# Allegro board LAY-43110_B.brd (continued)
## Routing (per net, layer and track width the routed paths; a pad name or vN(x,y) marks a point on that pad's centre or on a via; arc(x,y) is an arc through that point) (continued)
P1V8_3V3_BRD: length 233
  TOP w0.254: C35.1 74.46,28.68 71.92,28.68 71.5,29.1 U11.1 ; U7.8 17.79,33.71 C22.1 ; U17.6 19.56,18.97 19.7,19.1 19.95,19.1 20.59,19.74 v1(20.59,19.86) ; U12.6 18.97,30.28 C31.1 20.08,30.28 v1(20.71,30.91) ; v1(19.82,16.81) 19.82,16.69 C62.1 20.45,16.04 U20.6
  TOP w0.381: C22.1 18.05,32.94 v1(18.3,32.69)
  TOP w0.508: v1(18.3,32.69) 18.55,32.44 20.21,32.44 20.71,31.93 v1(20.71,30.91) ; C75.1 52.95,2.59 ; v1(71.92,25.76) 73.62,27.46 v1(73.62,27.99) 74.46,27.99 74.76,28.29 ; R21.1 R17.1 ; R17.1 v1(61.35,39.8) ; R17.1 R14.1 ; 74.76,28.29 74.89,28.17 76.95,28.17 77.91,29.13 77.91,32.61 v1(77.99,32.69) ; 74.76,28.29 C35.1 ; R39.1 61.4,32.33 61.4,29.03 v1(61.33,28.96) 61.73,28.55 R60.1 61.73,27.89 63.84,25.78 64,25.78 v1(64.02,25.76) ; R44.1 R41.1 77.48,33.2 v1(77.99,32.69) ; v1(77.99,32.69) 77.99,33.17 80.02,35.2 R30.1 88.46,35.2 v2(88.68,34.98) ; v1(72.63,35.64) 71.67,35.64 R32.1 ; v1(73.8,39.42) 73.8,39.7 C13.1 U3.6 ; R46.1 v1(63.94,31.88) ; R36.1 v1(91.55,35.51) ; v1(91.55,42.44) R9.1
  INT_1 w0.508: v2(88.68,34.98) 88.81,34.85 90.89,34.85 v1(91.55,35.51) v1(91.55,42.44) ; v1(73.62,27.99) 73.14,27.99 72.63,28.5 v1(72.63,35.64) 72.63,37.46 73.83,38.67 73.83,39.39 v1(73.8,39.42) ; v1(20.46,12.88) 23,12.88 24.88,11 32.63,11 34.94,8.69 45.1,8.69 46.24,7.54
  INT_1 w0.762: 46.24,7.54 48.83,4.95 51.17,4.95 52.95,3.17 52.95,2.59 54.93,4.57 56.73,4.57 58.03,3.28 58.03,2.59
  BOTTOM w0.508: v1(63.94,31.88) 61.33,29.26 v1(61.33,28.96) 61.07,28.7 59.17,28.7 57.29,26.82 52.06,26.82 51.12,25.88 SH17.2 v2(51.12,22) 51.12,21.44 54.75,17.81 61.28,17.81 67.32,11.76 67.32,8.97 68.23,8.06 68.95,8.06 J28.2 69.28,7.21 67.68,5.61 59.6,5.61 58.08,4.09 58.08,2.64 58.03,2.59 ; v1(73.8,39.42) 73.55,39.42 72.15,40.82 63.18,40.82 62.17,39.8 v1(61.35,39.8) ; v1(20.46,12.88) 19.82,13.51 v1(19.82,16.81) 19.82,18.47 20.59,19.23 v1(20.59,19.86) 19.44,21.01 19.44,29.64 v1(20.71,30.91) ; v1(71.92,25.76) v1(64.02,25.76)
P3V3_BATT: length 6.6
  TOP w0.508: D10.A 30.11,15.26 v1(30.54,15.7)
  BOTTOM w0.508: BT1.1 30.01,15.16 v1(30.54,15.7)
P3V3_LDO: length 62.1
  TOP w0.279: C39.1 68.8,26.29 69.16,26.65 U11.14
  TOP w0.508: v1(47.94,19.25) 52.82,19.25 53.48,18.59 61.73,18.59 63.51,20.37 63.51,22.4 66.81,25.7 C38.1 C39.1
  TOP w1.016: v1(47.94,19.25) 47.94,20.07 46.11,21.89 D8.C
  BOTTOM w1.016: J35.1 59.83,10.04 59.83,14.4 59.14,15.09 49.75,15.09 47.94,16.89 v1(47.94,19.25)
P3V3_SDA: length 159.3
  TOP w0.254: J14.1 C43.1 49.42,23.67 50.05,24.31 50.05,26.59 50.94,27.48 v1(51.07,27.48) ; R1.2 14.52,51.36 14.87,51.36 v1(15.13,51.1) ; v1(55.79,28.37) 55.89,28.47 R55.1 ; R5.1 v1(16.14,48.18) ; U4.1 52.62,39.9 C11.1 ; v1(50.66,41.1) 50.1,41.1 49.67,41.53 R10.1 ; v1(13.75,47.14) 13.3,47.6 C3.1 U1.1
  TOP w0.305: U6.7 52.8,34.66 52.69,34.54 v1(52.69,33.83) ; U5.7 39.92,37.2 39.61,36.9 v1(39.61,36.63) ; v1(52.69,30.84) 52.81,30.72 U13.1 ; U14.1 52.81,25.21 52.69,25.32 v1(52.69,25.86) ; U8.5 v1(46.8,34.16) ; U5.11 v1(42.19,35.2) ; v1(40.54,40.87) U5.1
  TOP w0.381: 39.69,41.68 C8.1 40.2,41.17 ; 36.49,41.3 C9.1 ; C9.1 37,40.79 ; C9.1 37.5,41.3 ; 39.99,40.54 U5.1 39.99,40.37 ; 38.72,40.41 C10.1 ; C10.1 37.96,41.05 ; C10.1 39.48,41.05
  TOP w0.508: v1(13.75,47.14) 14.24,46.66 R8.1 ; C11.1 v1(50.66,41.1) ; R43.1 v1(43.83,31.6) ; R42.1 v1(49.92,33.71) ; v1(56.73,40.51) 56.73,40.23 R16.1 ; v1(46.8,34.16) C20.1 ; v1(39.61,34.32) 40.14,33.78 R38.1 ; C29.1 v1(52.69,30.84) ; C42.1 51.65,25.86 v1(52.69,25.86) ; v1(18.55,40.54) 34.07,40.54 v1(34.4,40.21) ; C25.1 v1(52.69,33.83) ; v1(55.69,25.07) R65.1 ; R66.1 v1(44.39,24.69)
  INT_1 w0.254: v1(55.69,25.07) 56.35,25.73 56.35,27.81 v1(55.79,28.37)
  INT_1 w0.508: v1(43.83,31.6) 43.78,30.78 44.39,30.18 v1(44.39,24.69) ; v1(40.54,40.87) 40.54,37.86 39.61,36.93 v1(39.61,36.63) v1(39.61,34.32) ; v1(50.66,41.1) 51.45,41.1 52.69,39.85 v1(52.69,33.83) v1(52.69,30.84) 52.69,29.11 v1(51.07,27.48) v1(52.69,25.86) 52.69,25.48 53.61,24.56 55.26,24.56 55.69,24.99 v1(55.69,25.07)
  BOTTOM w0.508: v1(39.61,34.32) 41.3,34.32 v1(42.19,35.2) 43.23,34.16 v1(46.8,34.16) ; v1(40.54,40.87) 40.53,40.86 40.53,38.66 39.17,37.3 36.72,37.3 36.21,37.81 36.21,38.68 34.68,40.21 v1(34.4,40.21) ; v1(40.54,40.87) 39.74,40.87 SH16.1 ; v1(40.54,40.87) 41.17,40.87 41.88,40.16 48.78,40.16 49.72,41.1 v1(50.66,41.1) 51.63,41.1 53.2,39.52 54.57,39.52 55.56,40.51 v1(56.73,40.51) ; v1(15.13,51.1) 15.63,51.1 16.14,50.6 v1(16.14,48.18) 15.84,47.88 14.31,47.88 13.75,47.32 v1(13.75,47.14) 16.27,44.63 16.27,42.82 v1(18.55,40.54) ; v1(49.92,33.71) 49.72,33.91 49.54,33.91 48.6,34.85 47.49,34.85 v1(46.8,34.16) ; v1(46.8,34.16) 46.8,33.28 45.11,31.6 v1(43.83,31.6)
P5V: length 45.1
  TOP w0.254: U12.1 18.16,30.68 17.93,30.91 C32.1 ; v1(16.17,19.61) C54.1 17.16,19.61 17.8,18.97 U17.1 ; C24.1 17.19,33.61 U7.7 ; R50.1 v1(16.98,36.88) ; C61.1 17.42,16.04 U20.1
  TOP w0.381: R71.1 21.86,20.24 21.09,21.01 v1(20.59,21.01) ; C61.1 v1(17.41,16.81)
  TOP w0.508: C32.1 17.16,31.04 16.65,31.55 R45.2 16.4,31.17 v1(15.89,30.66) 15.38,30.15 R54.2 ; C41.1 9.16,24.82 9.03,24.82 ; C41.1 9.41,23.67 ; C41.1 10.3,24.88 ; C41.1 9.66,23.04 9.16,23.04 ; v1(8.78,19.48) 8.14,19.48 C53.1 8.78,18.34 U19.5 ; U15.4 22.24,23.67 v1(22.8,24.23) ; v1(16.01,17.83) 16.4,17.45 C59.1 U19.3 ; v1(28.21,26.47) 27.95,26.21 D13.A ; C24.1 v1(16.27,33.45)
  TOP w1.016: C41.1 U15.2 U15.4
  BOTTOM w0.508: v1(28.21,26.47) 27.95,26.21 24.85,26.21 22.87,24.23 v1(22.8,24.23)
  vias: v1(8.52,26.85) v1(8.52,25.7) v1(8.52,24.31) v1(8.52,23.16)
P5V0_SDA_USB_CONN_VBUS: length 5.4
  TOP w0.381: J11.1 5.88,43.39 TP5.1
  TOP w0.508: L1.1 7.96,45.29 D14.C 6.36,45.17 TP5.1
P5V_LDO_OUT: length 2.9
  TOP w0.508: 25.98,3.48 J34.3 ; J34.3 26.94,4.43 ; J34.3 26.94,2.53
P5V_SDA: length 53.3
  TOP w0.381: 35.22,36.02 37.88,36.02 39.57,37.71 U5.6
  TOP w0.508: R56.1 v1(42.58,30.48) R48.1 ; v1(33.41,30.53) 33.41,30.02 33.97,29.46 R52.1
  TOP w0.635: U9.1 35.21,32.8 ; C21.1 35.29,34.49
  TOP w1.016: v1(16.4,39.55) 33.54,39.55 33.9,39.19 33.9,39.01 ; C5.1 11.32,44.98 v1(11.32,45.77) 10.39,45.77 L1.2
  BOTTOM w0.508: v1(42.58,30.48) 38.32,30.48 37.35,29.51 34.18,29.51 33.41,30.28 v1(33.41,30.53)
  BOTTOM w0.635: v1(42.58,30.48) 44.4,30.48 TP35.1
  BOTTOM w1.016: v1(16.4,39.55) 15.63,39.55 14.62,40.56 14.62,42.72 11.57,45.77 v1(11.32,45.77)
P5V_SDA_PSW: length 15.5
  TOP w0.508: U9.6 v1(38.68,33.66)
  TOP w0.635: D3.A 27.24,34.27 D4.A 31.41,34.27 31.51,34.36 v1(32.58,34.36)
  BOTTOM w0.508: TP29.1 38.68,35.07 v1(38.68,33.66)
  BOTTOM w0.635: v1(38.68,33.66) 33.87,33.66 33.16,34.36 v1(32.58,34.36)
P5V_USB: length 69.6
  TOP w0.508: v1(25.03,8.31) 25.39,7.95 25.39,6.68 D12.C
  BOTTOM w0.508: v1(27.95,30.25) 25.82,28.12 22.87,28.12 21.48,26.72 21.48,15.54 25.03,11.99 v1(25.03,8.31) 25.03,7.47 25.69,6.81 41.77,6.81 47.66,0.91 58.89,0.91 60.57,2.59
P12V: length 46.7
  TOP w1.016: J32.1 21.35,8.81 19.95,7.42 10.05,7.42 9.16,8.31 D11.A 9.41,9.7 v1(10.55,9.7)
  INT_1 w1.016: v1(10.55,9.7) 3.57,9.7 J23.3 3.82,13 3.82,28.09 2.4,29.51 J13.2
P12V_VBAT: length 5.9
  TOP w0.508: U10.7 C33.1
  TOP w0.762: U10.7 9.54,30.28 9.56,30.3
  TOP w1.016: 9.16,12.24 D11.C 8.36,12.25 7.46,11.35 C68.1
VDD_1P45OUT_PMCIN: length 5.5
  TOP w0.254: 85.13,12.88 85.13,13.66 U18.15
  TOP w0.381: C66.1 84.11,11.13 85.13,12.14 85.13,12.88
  TOP w0.508: L5.1 83.76,10.41 C66.1
VDD_BRD: length 80.2
  TOP w0.381: v1(83.17,12.04) 83.76,12.62 C64.1 83.76,13.67 84.13,14.04 U18.13
  TOP w0.508: R69.1 v1(79.54,22.78)
  TOP w1.016: J29.1 J28.1 69.23,10.97 J27.1
  INT_1 w0.254: J12.1 59.91,28.14 59.55,27.79 59.55,22.28 58.84,21.56 56.76,21.56 55.26,20.07 52.31,20.07 51.73,19.48 50.97,19.48 49.7,18.21 49.7,13.67 53.02,10.34 55.65,10.34 J24.3
  INT_1 w0.508: v1(79.54,22.78) 79.54,21.77 81.6,19.71 81.6,14.45 83.17,12.88 v1(83.17,12.04) 83.17,11.79 81.47,10.08 73.42,10.08 J29.1
  BOTTOM w0.508: J24.3 59.02,8.4 60.46,6.96 62.85,6.96 64.2,8.31 64.2,9.68 J27.1
VDD_MCU: length 37.6
  TOP w0.152: U18.44 86.13,21.16
  TOP w0.254: 86.13,21.16 86.13,21.65 ; U18.20 87.63,13.27 C65.1 87.9,12.88 v1(88.28,12.88)
  TOP w0.381: v1(85.15,23.01) 85.42,22.75 C44.1 85.97,22.24 86.13,22.07 86.13,21.65
  TOP w0.508: v1(89.73,12.57) 91.63,12.57 L4.1
  INT_1 w0.508: 85.85,13.02 83.78,15.09 83.78,21.64 v1(85.15,23.01) ; 85.85,13.02 88.14,13.02 v1(88.28,12.88) 88.4,13 89.12,13 89.55,12.57 v1(89.73,12.57) ; 85.85,13.02 85.85,12.87 81.8,8.81 73.01,8.81 J29.2
VDD_RF: length 36.8
  TOP w0.254: U18.32 91.33,18.56 v1(91.48,18.41) 91.68,18.41 92,18.1 C78.1
  TOP w0.279: U18.35 90.81,20.06 C46.1 91.45,20.76 90.95,20.76 90.75,20.56 U18.36
  TOP w0.508: C46.1 91.48,21.36 v1(91.33,21.51) 91.76,21.95 C87.1 C86.1 91.78,23.36 91.78,24.36 91.12,25.02 v1(85.18,25.02)
  INT_1 w0.254: v1(91.48,18.41) 90.23,18.41 89.83,18.82 89.83,20.02 v1(91.33,21.51)
  INT_1 w0.508: v1(85.18,25.02) 84.54,25.02 83.2,23.67 79.08,23.67 78.04,22.63 78.04,21.31 76.53,19.8 74.32,19.8 J31.2
VDD_RFF: length 15.6
  TOP w0.508: L5.2 C67.1 80.43,9.88 79.79,10.52 v1(79.79,11.1)
  INT_1 w0.508: v1(79.79,11.1) 78.68,12.22 76.03,12.22 J31.1
  INT_1 w1.016: J30.2 J31.1
VDDA: length 5.1
  TOP w0.254: C69.1 91.63,16.56 U18.28
  TOP w0.381: C69.1 92.21,16.08 92.77,15.52 92.77,14.73 L4.2
A0: length 3
  TOP w0.152: R99.2 73.04,5.26 73.04,2.82 J4.1
A1: length 2.8
  TOP w0.152: SH13.2 J4.2
A2: length 2.9
  TOP w0.152: J4.3 78.4,5.33 SH14.2
A3: length 3
  TOP w0.152: SH15.2 80.94,4.72 J4.4
A4: length 2.7
  TOP w0.152: R96.2 82.49,3.53 J4.5
A5: length 4.2
  TOP w0.152: J4.6 86.02,4.8 R100.2 R97.2
ADC0_DM0/CMP0_IN1: length 72.6
  TOP w0.152: v1(79.84,27.89) 79.77,27.97 79.77,33.2 80.43,33.86 89.07,33.86 90.21,35 90.21,37.62 89.42,38.4 88.25,38.4 87.9,38.76 R19.1 ; R97.1 84.42,6.32 84.9,5.84 85.18,5.84 v1(85.23,5.79) 85.36,5.92 85.36,6.88 84.37,7.87 81.57,7.87 81.29,8.15 75.96,8.15 v1(75.37,7.57) ; v1(91.07,14.25) 90.61,14.25 90.34,14.52 U18.25
  INT_1 w0.152: v1(91.07,14.25) 91.4,13.92 91.4,10.87 90,9.47 88.96,9.47 85.28,5.79 v1(85.23,5.79)
  BOTTOM w0.152: v1(79.84,27.89) 79.03,27.08 76.44,27.08 75.15,25.78 75.15,7.8 v1(75.37,7.57)
ADC0_DP0/CMP0_IN0: length 70.3
  TOP w0.152: v1(78.85,27.99) 79.26,28.4 79.26,33.35 80.18,34.26 88.96,34.26 89.79,35.09 89.79,37.48 89.24,38.02 88.2,38.02 87.9,37.72 R25.1 ; R99.1 74.69,6.17 74.84,6.32 v1(75.04,6.32) ; v1(90.91,13.46) 90.8,13.46 90.45,13.82 89.83,13.82 89.63,14.01 U18.24
  INT_1 w0.152: v1(75.04,6.32) 75.12,6.32 75.76,5.69 84.47,5.69 88.61,9.83 89.78,9.83 90.91,10.96 v1(90.91,13.46)
  BOTTOM w0.152: v1(75.04,6.32) 74.78,6.59 74.78,26.17 76.09,27.48 78.35,27.48 v1(78.85,27.99)
ANT: length 3.3
  TOP w0.203: L2.1 C50.1 90.36,19.08 U18.33
BYP_FXOS8700CQ: length 4.3
  TOP w0.203: C34.1 73.95,29.24 72,29.24 71.63,29.6 U11.2
CAN_HI: length 9
  TOP w0.254: v1(6.49,14.78) 7,14.78 7.58,15.37 R77.2 U19.7
  BOTTOM w0.254: J23.1 2.04,15.67 2.93,14.78 v1(6.49,14.78)
CAN_LO: length 11.5
  TOP w0.254: U19.6 8.22,17.07 R73.1 7.58,17.27 7,16.69 v1(6.74,16.69)
  BOTTOM w0.254: 2.04,13.77 2.3,14.02 6.62,14.02 7.38,14.78 7.38,16.05 v1(6.74,16.69)
CAN_RX: length 3.4
  TOP w0.152: U17.3 16.77,17.97 16.4,18.34 U19.4
CAN_TX: length 4.7
  TOP w0.152: 14.78,14.53 15.76,14.53 16.27,14.02 18.05,14.02 18.56,14.53 U20.3
CRST_FXOS8700CQ: length 3.3
  TOP w0.203: U11.8 69.16,34.06 69.2,34.1 C19.1
CS: length 4.1
  TOP w0.152: R23.2 R21.2 TP14.1 65.84,38.79 U3.4
D0: length 8.7
  TOP w0.152: J8.2 87.52,44.88 87.52,49.31 J1.1
D1: length 4.9
  TOP w0.152: J10.2 83.45,45.94 J1.2
D2: length 3.7
  TOP w0.152: J1.3 80.91,47.68 80.92,47.66 SH11.2
D3: length 4.3
  TOP w0.152: J1.4 79.76,49.45 SH10.2
D4: length 4.2
  TOP w0.152: SH9.2 75.83,48.43 75.83,50.84
D5: length 4.2
  TOP w0.152: J1.6 73.29,48.43 SH8.2
D6: length 3.7
  TOP w0.152: J1.7 70.75,49.81 70.74,49.8 SH7.2
D7: length 3.7
  TOP w0.152: SH6.2 68.21,47.16 J1.8
D8: length 3.7
  TOP w0.152: J2.1 64.22,49.78 64.24,49.77 SH5.2
D9: length 3.7
  TOP w0.152: SH2.2 61.67,49.77 61.68,49.78 J2.2
D10: length 3.7
  TOP w0.152: J2.3 59.14,49.78 59.13,49.77 SH4.2
D11: length 5.1
  TOP w0.152: J2.4 56.6,46.5 J9.2
D12: length 8.6
  TOP w0.152: J7.2 52.34,44.52 52.34,49.09 J2.5
D13: length 4.1
  TOP w0.152: J2.6 51.52,49.28 50.29,48.04 SH1.2
D14: length 3.8
  TOP w0.152: J2.9 43.9,49.4 R7.2
D15: length 6.2
  TOP w0.152: R6.1 43.43,46.16 41.36,48.23 J2.10
DCDC_LN: length 9.8
  TOP w0.279: U18.14 v2(84.63,13.34) ; U18.12 82.54,15.06 v2(82.54,15.06) 81.98,15.06
  TOP w0.381: 81.98,15.06 81.67,15.06 79.47,12.86 L3.2
  BOTTOM w0.279: v2(84.63,13.34) 82.9,15.06 v2(82.54,15.06)
DCDC_LP: length 5.2
  TOP w0.279: 81.56,16.06 U18.10
  TOP w0.381: L3.1 78.6,16.06 81.56,16.06
EXTAL_32M: length 5.7
  TOP w0.152: U18.30 91.39,17.56 92.27,16.69 92.98,16.69 93.33,16.33 94.65,16.33 95.13,15.86 Y1.3
I2C1_SCL: length 5.2
  TOP w0.203: U11.4 72.98,30.6 TP20.1 73.09,30.61 74.28,30.61 R47.1 74.82,31.14 R44.2
I2C1_SDA: length 7.9
  TOP w0.203: R41.2 R37.1 73.42,34.21 TP17.1 70.75,33.83 70.16,33.24 U11.6
INT1_COMBO_R: length 4.2
  TOP w0.203: U11.11 66.84,30.1 R61.1
INT2_COMBO: length 3.2
  TOP w0.203: R40.2 R39.2 62.8,32.87 v1(63.51,33.58)
  BOTTOM w0.203: TP32.1 63.23,33.3 v1(63.51,33.58)
INT2_COMBO_R: length 4.1
  TOP w0.203: R40.1 66.6,31.1 U11.9
LEDRGB_BLUE: length 2
  TOP w0.254: R93.2 40.88,8.95 LED4.3
LEDRGB_GREEN: length 1.9
  TOP w0.254: LED4.4 42.42,8.99 R90.2
LEDRGB_RED: length 4.3
  TOP w0.254: LED4.1 42.41,11.98 42.41,13.61 43.22,14.43 R87.2
LIN: length 13.2
  TOP w0.254: U10.6 C28.1 2.55,31.55 J13.1
  TOP w0.508: R27.1 R34.1 3.31,34.72 2.04,33.45 J13.1
LIN_RX_LS: length 4.8
  TOP w0.152: U12.3 17.67,29.27 17.28,28.88 R54.1 15.25,29.01 13.63,29.01
LIN_SLP: length 7.3
  TOP w0.152: U7.6 16.4,35.1 15.63,34.34 15.63,32.82 15.38,32.56 R45.1 15.38,31.04 14.62,30.28 U10.2
LIN_TX_LS: length 5.5
  TOP w0.152: U10.4 14.87,32.82 15.13,33.07 15.13,34.34 16.39,35.6 U7.5
LVLRST_EN: length 1.2
  TOP w0.152: R1.1 13.35,51.36 13.3,51.31 U1.5
MIC2005_CSLEW: length 3.5
  TOP w0.254: U9.5 38.06,31.85 37.45,32.46 C21.2
P5-9V_VIN: length 75.7
  TOP w0.381: J34.1 32.97,3.48 ; J34.1 31.06,3.48 ; J34.1 32.02,4.43 ; J34.1 32.02,2.53
  TOP w0.508: v1(29.22,17.07) 29.35,16.94 29.35,14.25 28.71,13.61 28.71,12.78 26.81,10.87 v1(26.81,7.8) ; D6.A v1(28.21,28.65)
  INT_1 w0.508: v1(28.21,28.65) 28.46,28.65 29.22,27.89 v1(29.22,17.07) ; v1(26.81,7.8) 26.94,7.8 31.25,3.48 J34.1 36.31,7.77 42.41,7.77 49.01,1.17 66.76,1.17 68.19,2.59
P5-9V_VIN_VR: length 9
  TOP w0.508: 25.03,25.07 25.65,24.45 v1(25.68,24.45) ; TP21.1 24.18,22.78 U16.3
  TOP w0.635: C40.1 27.8,24.56 25.79,24.56 v1(25.68,24.45)
  TOP w1.016: U16.3 24.18,26.12 D13.C
P_LED: length 15.1
  TOP w0.254: R70.1 SH12.1 LED2.A
  TOP w0.508: R70.1 41.77,17.83 42.33,17.27 42.33,15.8 40.86,14.33 LED3.A 38.6,13.43 39.97,12.07 40.79,12.07 LED4.2
POWER_EN: length 15.9
  TOP w0.152: U5.31 v1(41.69,42.42) ; v1(40.14,29.46) R53.1
  INT_1 w0.152: v1(40.14,29.46) 40.47,29.79 40.47,33.75 41.69,34.97 v1(41.69,42.42)
PSWITCH: length 20
  TOP w0.254: U18.8 82.52,17.06 80.1,19.48 78.6,19.48 77.91,20.17 67.98,20.17 66.08,18.26 65.49,18.26 J38.2
PSWTICH_CON: length 14.1
  TOP w0.152: J38.1 65.48,20.69 62.04,17.25 R63.1 C36.1 56.58,17.53 53.67,17.53 SW4.1
PTA0/SWD_DIO: length 39.7
  TOP w0.152: J12.2 58.64,29.59 62.08,26.15 62.08,24.04 61,22.96 J16.2 v1(62.31,21.48) ; U18.1 83.21,20.56 82.82,20.96 82.82,23.16 82.28,23.7 78.55,23.7 77.74,22.89 74.54,22.89 74.38,23.04 73.39,23.04 v1(73.11,23.32)
  INT_1 w0.152: v1(73.11,23.32) 73.06,23.32 72.91,23.16 72.91,21.59 71.82,20.5 69.96,20.5 69.2,21.26 67.58,21.26 66.69,22.15 63.72,22.15 63.04,21.48 v1(62.31,21.48)
  BOTTOM w0.152: TP38.1 62.32,21.49 v1(62.31,21.48)
PTA1/SWD_CLK: length 29.4
  TOP w0.152: v1(72.38,23.8) 72.38,23.16 72.83,22.71 74.26,22.71 74.46,22.5 78.07,22.5 78.93,23.37 81.9,23.37 82.46,22.81 82.46,20.5 82.9,20.06 U18.2
  BOTTOM w0.152: TP36.1 60.97,27.19 60.97,25.65 J15.1 62.22,24.1 72.05,24.1 72.35,23.8 v1(72.38,23.8)
PTA16: length 74.6
  TOP w0.152: v1(63,46.02) 64.14,46.02 SH5.1 ; U18.4 82.78,19.06 80.71,21.13 79.49,21.13 78.93,21.69 74.16,21.69 73.83,22.02 v1(71.72,22.02) 71.13,22.61 70.29,22.61 68.97,21.29 67.3,21.29 66.43,22.15 64.53,22.15 64.15,21.77 64.15,19.99 62.12,17.96 51.65,17.96 50.91,17.22 50.91,13.18 50.63,12.9 R82.2
  INT_1 w0.152: v1(71.72,22.02) 71.72,25.2 70.73,26.19 67.98,26.19 63.03,31.14 63.03,36.37 62.06,37.34 62.06,45.57 62.52,46.02 v1(63,46.02)
PTA17: length 115.1
  TOP w0.152: SH9.1 76.12,45.14 75.7,45.14 75.04,44.48 58.84,44.48 v1(58.75,44.56) ; R58.2 21.98,28.63 v1(22.87,29.51) ; 83.53,18.56 U18.5 82.85,18.56 80.66,20.75 79.29,20.75 78.69,21.35 74.04,21.35 73.75,21.64 72.78,21.64 72.48,21.34 71.82,21.34 v1(71.79,21.31) ; v1(26.94,43.54) 28.74,45.34 33.52,45.34 34.63,44.22 v1(49.62,44.22)
  INT_1 w0.152: v1(22.87,29.51) 23.25,29.9 23.25,34.59 23.86,35.2 25.36,35.2 27.6,37.44 27.6,41.71 26.94,42.37 v1(26.94,43.54) ; v1(49.62,44.22) 49.85,44.45 58.64,44.45 v1(58.75,44.56) 58.75,38.09 62.12,34.72 62.12,26.85 66.03,22.94 68.19,22.94 69.79,21.34 71.77,21.34 v1(71.79,21.31)
PTA18: length 100.5
  TOP w0.152: v1(25.21,36.27) 22.72,36.27 21.68,35.23 R28.2 ; U18.6 82.87,18.06 80.56,20.37 79.06,20.37 78.45,20.98 73.49,20.98 v1(73.34,21.13) ; v1(25.93,43.52) 28.41,46 33.74,46 35.14,44.6 48.96,44.6 v1(49.52,45.16) ; v1(73.67,26.29) 73.67,24.66 73.27,24.26 v1(73.24,24.26) ; v1(69.76,45.87) 70.48,45.87 SH7.1
  INT_1 w0.152: v1(25.21,36.27) 25.21,37.82 25.93,38.54 v1(25.93,43.52) ; v1(73.24,24.26) 73.72,23.77 73.72,21.51 v1(73.34,21.13) ; v1(73.67,26.29) 73.67,26.54 74.94,27.81 74.94,34.21 74.54,34.62 74.54,42.9 73.7,43.74 71.13,43.74 69.76,45.11 v1(69.76,45.87) 69.66,45.87 68.69,46.84 52.31,46.84 51.12,45.64 50,45.64 v1(49.52,45.16)
PTA19: length 49.1
  TOP w0.152: R60.2 R61.2 63.97,27.69 63.59,27.3 v1(63.59,27.25) ; U18.7 82.76,17.56 80.33,19.99 78.85,19.99 78.24,20.6 71.54,20.6 70.83,21.31 v1(70.83,21.97) ; v1(59.46,45.07) 59.39,45.07 59.13,45.33 SH4.1
  INT_1 w0.152: v1(70.83,21.97) 71.07,22.21 71.07,23.99 70.37,24.69 65.87,24.69 63.59,26.97 v1(63.59,27.25) 63.49,27.25 62.65,28.09 62.65,34.87 60.85,36.68 60.85,43.69 v1(59.46,45.07)
PTB0: length 93
  TOP w0.152: R47.2 75.88,31.12 v1(76.44,30.56) ; R6.2 43.18,47.69 v1(43.01,47.52) ; U18.16 85.61,14.33 v1(85.61,8.25) 85.98,7.89 R100.1
  INT_1 w0.152: v1(77.53,6.65) 77.71,6.48 83.83,6.48 v1(85.61,8.25) ; v1(77.23,25.02) 77.08,25.17 77.08,26.06 76.21,26.92 76.21,30.33 v1(76.44,30.56) 75.91,31.09 75.91,42.85 73.67,45.09 72.35,45.09 70.92,46.52 70.92,47.26 69.96,48.21 47.61,48.21 46.39,46.99 43.37,46.99 43.01,47.35 v1(43.01,47.52)
  BOTTOM w0.152: v1(77.53,6.65) 77.41,6.78 77.41,8.03 77.23,8.2 v1(77.23,25.02)
PTB1: length 87.5
  TOP w0.152: v1(83.25,7.11) 83.25,6.98 82.59,6.32 R96.1 ; R7.1 46.23,46.16 v1(46.57,46.51) ; v1(75.27,35.23) 75.55,35.23 75.83,34.95 R37.2 ; v1(86.13,9.51) 85.94,9.7 85.94,13.69 86.13,13.88 U18.17
  INT_1 w0.152: v1(76.77,7.29) 76.87,7.19 77.91,7.19 78.24,6.86 82.99,6.86 v1(83.25,7.11) 83.25,7.44 84.7,8.89 85.41,8.89 86.03,9.51 v1(86.13,9.51) ; v1(46.57,46.51) 47.87,47.8 69.61,47.8 70.27,47.14 70.27,46.51 72.07,44.7 73.37,44.7 75.37,42.7 75.37,35.33 v1(75.27,35.23) 75.45,35.05 75.45,26.72 76.34,25.83 76.34,25.04 v1(76.45,24.93)
  BOTTOM w0.152: v1(76.45,24.93) 76.87,24.51 76.87,7.67 76.77,7.57 v1(76.77,7.29)
PTB2: length 44.4
  TOP w0.152: R89.2 50.05,8.94 54.52,8.94 57.26,6.2 73.77,6.2 74.49,6.91 75.58,6.91 76.52,7.85 78.19,7.85 78.35,7.7 v1(78.35,7.65) SH14.1 ; v1(86.4,11.02) 86.4,13.67 86.63,13.9 U18.18
  INT_1 w0.152: v1(86.4,11.02) 85.15,9.78 84.32,9.78 82.66,8.13 80.33,8.13 79.84,7.65 v1(78.35,7.65)
PTB3: length 70.2
  TOP w0.152: v1(80.71,7.67) 80.33,7.29 SH15.1 80.15,6.35 79.64,5.84 79.64,1.6 79.06,1.02 72.5,1.02 71.84,1.68 71.84,5.31 71.29,5.87 56.68,5.87 54.24,8.31 51.63,8.31 51.09,7.77 51.09,6.63 50.15,5.69 40.55,5.69 39.66,6.58 39.66,10.39 39.03,11.02 R92.1 ; U18.19 87.13,13.81 86.91,13.59 86.91,10.49 v1(86.75,10.34)
  INT_1 w0.152: v1(80.71,7.67) 82.77,7.67 84.47,9.37 85.26,9.37 86.09,10.21 86.63,10.21 v1(86.75,10.34)
PTB16/XTAL_32K: length 4.3
  TOP w0.203: Y2.1 88.3,10.99 88.84,11.53 88.84,13.11 88.13,13.81 U18.21
PTB17/EXTAL_32K: length 5.1
  TOP w0.203: Y2.2 90.03,10.59 89.24,11.38 89.24,13.28 88.63,13.9 U18.22
PTB18: length 76.2
  TOP w0.152: v1(80.71,28.07) 80.15,28.63 80.15,32.99 80.61,33.45 87.41,33.45 v1(87.74,33.12) ; U18.23 89.13,13.98 89.86,13.26 v1(90.18,13.26) ; v1(76.77,6.4) SH13.1 ; 93.74,44.5 SW2.1 R9.2 C7.1 89.17,44.5 TP6.1 v1(88.66,42.98)
  INT_1 w0.152: v1(88.66,42.98) 88.05,42.37 88.05,35.76 87.74,35.46 v1(87.74,33.12) ; v1(90.18,13.26) 90.49,12.95 90.49,11.58 90,11.1 89.24,11.1 84.21,6.07 77.1,6.07 v1(76.77,6.4)
  BOTTOM w0.152: v1(76.77,6.4) 76.67,6.4 76.21,6.86 76.21,8.48 75.58,9.12 75.58,25.58 76.67,26.67 79.54,26.67 80.71,27.84 v1(80.71,28.07)
PTC1: length 81.2
  TOP w0.152: R76.1 v2(50.71,17.65) ; SH2.1 61.67,45.58 62.09,45.16 v1(62.98,45.16) ; C79.1 90.28,22.61 v2(89.75,22.07) 89.63,21.95 U18.37
  INT_1 w0.152: v2(50.71,17.65) 52.62,17.65 53.91,18.95 61.63,18.95 62.55,19.86 73.19,19.86 74.23,20.9 74.23,24.26 ; v2(89.75,22.07) 89.73,22.05 89.73,22.02 89.27,21.56 86.7,21.56 86.07,22.2 86.07,25.6 85.46,26.21 84.21,26.21 83.1,25.1 78.5,25.1 77.66,24.26 74.23,24.26 ; 74.23,24.26 71.77,26.72 68.08,26.72 64.53,30.28 64.53,35.61 63.26,36.88 63.26,44.88 v1(62.98,45.16)
PTC2: length 18.8
  TOP w0.152: 93.74,33.71 SW3.1 R36.2 C23.1 89.67,33.71 TP18.1 88.79,32.46 v1(89.42,31.83) ; U18.38 89.13,21.99 v2(89.22,22.07) 89.32,22.17 C80.1
  INT_1 w0.152: v1(89.42,31.83) 90.34,30.91 90.34,26.04 89.57,25.27 89.57,24.23 89.17,23.83 89.17,22.12 v2(89.22,22.07)
PTC3: length 124.5
  TOP w0.152: v1(22.39,15.8) 22.77,15.42 22.77,14.68 R81.2 ; C81.1 88.68,22.42 v2(88.68,22.07) 88.63,22.02 U18.39 ; SH10.1 79.76,46.06 v1(78.32,44.63)
  INT_1 w0.152: v1(22.39,15.8) 21.58,16.61 21.58,36.2 22.09,36.7 22.09,43.13 25.46,46.51 39.41,46.51 42.18,49.28 73.93,49.28 78.32,44.88 v1(78.32,44.63) 78.52,44.42 78.52,34.49 80.94,32.08 85.2,32.08 88.24,29.04 88.24,25.44 88.71,24.97 88.71,24.18 88.56,24.03 88.56,22.2 v2(88.68,22.07)
PTC4: length 118.2
  TOP w0.152: SH8.1 75.78,46.13 v1(75.84,46.19) ; C82.1 87.48,22.75 88.13,22.09 v2(88.13,22.07) U18.40 ; R74.2 21.86,17.35 v1(22.72,18.21)
  INT_1 w0.152: v2(88.13,22.07) 88.02,22.18 88.02,24.74 87.73,25.03 87.73,28.92 85.03,31.62 80.71,31.62 78.14,34.19 78.14,43.89 v1(75.84,46.19) 75.72,46.19 72.96,48.95 42.68,48.95 39.81,46.08 25.69,46.08 22.54,42.93 22.54,36.55 22.03,36.04 22.03,18.9 v1(22.72,18.21)
PTC5: length 103.6
  TOP w0.152: R35.2 23.06,35.67 v1(24.27,35.67) ; v1(73.57,45.59) 73.27,45.29 69.15,45.29 68.31,46.13 SH6.1 ; U18.41 87.63,22.03 v2(87.59,22.07)
  INT_1 w0.152: v1(24.27,35.67) 24.75,36.16 24.75,44.3 26.07,45.62 40.25,45.62 43.27,48.64 70.52,48.64 v1(73.57,45.59) 75.76,45.59 77.74,43.61 77.74,33.86 81.17,30.43 84.49,30.43 87.19,27.74 87.19,24.38 87.64,23.93 87.64,22.12 v2(87.59,22.07)
PTC16: length 56.9
  TOP w0.152: SH1.1 50.29,44.08 52.08,42.29 60.11,42.29 60.82,41.58 v1(61.48,41.58) 61.73,41.83 R13.1 ; U18.45 85.63,21.85 84.29,23.19 84.29,27.56 84,27.85 v1(84,28.44)
  INT_1 w0.152: v1(77.18,40.92) 77.3,40.79 77.3,32.46 80,29.77 82.66,29.77 v1(84,28.44)
  BOTTOM w0.152: v1(61.48,41.58) 62.42,41.58 63.54,42.7 75.48,42.7 77.18,41 v1(77.18,40.92)
PTC17: length 48.7
  TOP w0.152: v1(82.8,28.61) 82.8,28.33 83.93,27.2 83.93,22.99 85.13,21.79 U18.46 ; v1(76.42,43.38) 76.37,43.38 76.29,43.46 62.85,43.46 R11.1 62.09,43 56.39,43 J9.1
  INT_1 w0.152: v1(82.8,28.61) 79.43,28.61 76.34,31.7 76.34,43.31 v1(76.42,43.38)
PTC18: length 55.3
  TOP w0.152: J7.1 54.87,44.53 57.7,44.53 58.23,43.99 79.06,43.99 v1(79.44,43.61) 78.42,42.6 R12.2 ; U18.47 84.63,21.71 83.55,22.78 83.55,26.95 81.67,28.83 81.67,32.69 v1(81.83,32.84)
  INT_1 w0.152: v1(79.44,43.61) 81.83,41.22 v1(81.83,32.84)
PTC19: length 44.5
  TOP w0.152: R23.1 63.61,37.41 74.46,37.41 75.45,38.4 78.47,38.4 v1(79.03,38.96) 79.03,41.86 80.92,43.75 SH11.1 ; v1(81.01,32.87) 81.17,32.72 81.17,28.78 83.15,26.8 83.15,22.58 84.13,21.6 U18.48
  INT_1 w0.152: v1(81.01,32.87) 81.19,33.05 81.19,33.59 79.03,35.75 v1(79.03,38.96)
RF_50: length 7.7
  TOP w0.203: L2.2 C51.1 C57.1
RF_ANT: length 1.8
  TOP w0.203: R72.2 108.32,19.07
RF_SMA: length 5.4
  TOP w0.203: J21.1 102.4,12.7 C57.2
RST_FXOS8700CQ: length 5.6
  TOP w0.203: R67.1 71.64,24.93 70.87,25.7 R64.2
  TOP w0.279: U11.16 70.16,26.38 70.07,26.29 R64.2
RST_TGTMCU_B: length 131.2
  TOP w0.152: v1(48.43,45.16) 48.22,44.96 35.65,44.96 34.07,46.53 30.87,46.53 28.46,48.95 TP3.1 ; R2.2 12.03,50.65 12.03,49.81 12.23,49.61 U1.7
  TOP w0.203: v1(55.64,33.58) 56.65,33.58 58.53,35.46 J12.10 ; v1(67.7,21.82) 68.64,21.82 70.19,23.37 R67.2 71.64,23.19 72.45,22.38 74.03,22.38 74.33,22.07 79.29,22.07 79.59,21.77 R69.2 C47.1 81.47,21.77 81.82,21.42 81.82,20.61 82.87,19.56 U18.3 ; v1(63.54,17.04) 62.7,16.21 60.74,16.21 59.42,14.88 59.42,7.49 v1(58.97,7.04)
  TOP w0.254: 23.51,50.47 R3.2 TP3.1 ; R2.2 v1(10.58,51.23)
  INT_1 w0.152: v1(67.7,21.82) 66.99,22.53 65.93,22.53 61.73,26.72 61.73,34.59 60.21,36.12 59.3,36.12 J12.10 ; v1(55.64,33.58) 55.26,33.96 55.26,40.56 53.51,42.32 50.53,42.32 48.6,44.25 48.6,44.98 v1(48.43,45.16)
  BOTTOM w0.203: 55.49,2.59 55.49,3.05 58.97,6.53 v1(58.97,7.04) ; v1(63.54,17.04) 63.94,17.45 63.94,21.41 64.55,22.02 67.4,22.02 67.6,21.82 v1(67.7,21.82)
  BOTTOM w0.254: 23.51,50.47 22.24,51.74 10.91,51.74 10.58,51.41 v1(10.58,51.23)
SA0_FXOS8700CQ: length 4.8
  TOP w0.203: R32.2 71.09,34.65 71.09,34.65 R31.1 69.66,33.89 U11.7
SA1_FXOS8700CQ: length 4.9
  TOP w0.203: R46.2 64.96,30.57 64.95,30.56 R51.1 65.64,30.6 U11.10
SCK: length 4
  TOP w0.152: U3.2 64.55,41.35 TP11.1 64.4,41.33 63.89,41.83 R13.2 R14.2
SDA_EXTAL: length 5.1
  TOP w0.152: U5.17 46.32,36.7 C18.1 48.17,35.38 48.41,35.62 X1.3
SDA_JTAG_TCLK: length 15.5
  TOP w0.152: U5.12 42.69,33.13 40.6,31.04 40.6,27.53 42.86,25.27 45.35,25.27 J14.4
SDA_JTAG_TDI: length 9.6
  TOP w0.152: v1(43.19,35.13) U5.13
  INT_1 w0.152: J14.8 45,28.17 45,30.53 44.39,31.14 44.39,33.93 v1(43.19,35.13)
SDA_JTAG_TDO: length 14.1
  TOP w0.152: U5.14 43.69,33.57 41.59,31.47 41.59,27.43 42.81,26.21 J14.6
SDA_JTAG_TMS: length 17.8
  TOP w0.152: J14.2 v1(44.46,23.67) R66.2 ; v1(42.91,32.13) 43.27,32.13 44.19,33.05 U5.15
  INT_1 w0.152: v1(42.91,32.13) 42.33,32.13 41.9,31.7 41.9,25.1 43.32,23.67 v1(44.46,23.67)
SDA_LED: length 4.7
  TOP w0.152: D1.C TP8.1 43.07,42.85 v1(42.96,42.75) 42.96,42.29 42.69,42.02 U5.29
SDA_LED_R: length 1.5
  TOP w0.152: 48.65,42.85 D1.A
SDA_RST: length 14.9
  TOP w0.152: R49.1 v1(45.68,30.48) ; v1(45.68,30.48) 45.68,28.75 ; v1(45.68,30.48) R48.2 ; v1(46.19,37.71) U5.19
  INT_1 w0.152: v1(46.19,37.71) 44.97,36.49 44.97,31.19 v1(45.68,30.48)
  BOTTOM w0.152: v1(45.68,30.48) 46.14,30.48 TP34.1
SDA_RST_LED: length 1.3
  TOP w0.152: LED1.A R8.2
SDA_RST_TGTMCU_B: length 28.9
  TOP w0.152: J6.2 25.51,44.4 v1(25.82,44.4) ; U5.21 46.21,38.71 v1(46.22,38.71)
  INT_1 w0.152: v1(46.22,38.71) 46.22,42.11 44.08,44.25 25.97,44.25 v1(25.82,44.4)
SDA_RST_TGTMCU_J_B: length 21.6
  TOP w0.254: R3.1 26.68,49.33 25.72,48.36 22.67,48.36 J6.1 ; LED1.C 18.43,46.77 J5.1 16.93,50.47 15.66,49.2 R5.2 15.25,49.21 U1.2
  BOTTOM w0.254: J5.1 18.43,47.8 19.7,46.53 J6.1
SDA_RX_EN: length 1
  TOP w0.152: U4.5 R16.2
SDA_SPI0_SCK: length 28.3
  TOP w0.152: U14.3 v1(52.85,22.5) ; v1(47.05,41.33) 46.6,41.33 46.44,41.48 44.34,41.48 44.19,41.33 U5.26
  INT_1 w0.152: v1(47.05,41.33) 47.05,38.53 48.93,36.65 48.93,24.03 50.46,22.5 v1(52.85,22.5)
  BOTTOM w0.152: TP37.1 53.3,22.5 v1(52.85,22.5)
SDA_SPI0_SIN: length 15.3
  TOP w0.152: U5.28 43.19,41.7 43.57,42.09 48.22,42.09 48.83,41.48 v1(48.83,41.38) ; U6.5 52.27,36.64 51.96,36.96 51.96,38.13 50.58,39.5 49.85,39.5 49.59,39.75 v1(49.49,39.75)
  INT_1 w0.152: v1(49.49,39.75) 49.49,39.85 48.83,40.51 v1(48.83,41.38)
  BOTTOM w0.152: TP28.1 50.28,40.18 49.78,39.68 49.56,39.68 v1(49.49,39.75)
SDA_SPI0_SOUT: length 21.4
  TOP w0.152: U13.3 51.62,28.84 50.55,29.91 v1(50.55,31.17) ; v1(47.84,41.43) 47.49,41.78 43.88,41.78 43.69,41.59 U5.27
  INT_1 w0.152: v1(47.84,41.43) 47.84,38.66 50.55,35.95 v1(50.55,31.17)
  BOTTOM w0.152: v1(50.55,31.17) 50.42,31.04 TP33.1
SDA_SWD_EN: length 23.4
  TOP w0.152: v1(55.08,22.15) 55.38,22.45 55.38,23.42 54.75,24.05 R65.2 U14.5 ; v1(45.66,33.04) U8.6
  INT_1 w0.152: v1(45.66,33.04) 46.93,33.04 48.35,31.62 48.35,23.47 50.41,21.41 54.34,21.41 v1(55.08,22.15)
SDA_SWD_EN_B: length 5.4
  TOP w0.152: U5.16 44.69,32.61 R43.2 45.12,32.04 U8.1
SDA_SWD_OE: length 17.9
  TOP w0.152: U13.5 54.83,29.34 R55.2 55.23,29.03 55.23,28.4 54.8,27.97 51.47,27.97 50.05,29.39 50.05,31.8 50.53,32.28 50.53,34.06 50.05,34.54 47.87,34.54 47.3,33.98 U8.4
SDA_SWD_OE_B: length 11.2
  TOP w0.152: U8.3 47.54,31.8 49.03,31.8 R42.2 49.34,32.16 48.04,33.45 v1(48.02,33.45) ; U5.20 45.9,38.21 45.9,38.2 v1(46.72,38.2)
  INT_1 w0.152: v1(46.72,38.2) 48.32,36.6 48.32,33.76 v1(48.02,33.45)
SDA_USB_CONN_DN: length 41.9
  TOP w0.292: D16.1 7.29,42.71 5.57,42.71 v1(5.51,42.77) 5.35,42.77 5.31,42.74 J11.2 ; v1(11.19,41.65) 11.68,41.65 TP12.1 12.45,41.88 33.8,41.88 35.26,40.42 35.26,39.77 36.13,38.89 36.65,38.89 36.94,38.6 R22.1
  BOTTOM w0.292: v1(5.51,42.77) 5.35,42.77 5.17,42.6 4.79,42.6 4.27,42.08 4.27,41.29 4.82,40.74 7.18,40.74 8.14,41.71 11.13,41.71 v1(11.19,41.65)
SDA_USB_CONN_DP: length 40.4
  TOP w0.292: J11.3 v1(5.51,42.09) 5.64,42.21 7.04,42.21 D15.1 ; v1(11.19,42.34) 11.49,42.34 TP7.1 12.42,42.33 33.98,42.33 35.7,40.61 35.7,39.95 36.32,39.34 36.73,39.34 R18.1
  BOTTOM w0.292: v1(5.51,42.09) 5.35,42.09 5.28,42.15 4.97,42.15 4.71,41.89 4.71,41.48 5,41.19 6.99,41.19 7.96,42.15 11,42.15 v1(11.19,42.34)
SDA_USB_DN: length 2.7
  TOP w0.254: U5.4 40.51,38.73 38.32,38.73
  TOP w0.292: R22.2 38.32,38.73
SDA_USB_DP: length 2.7
  TOP w0.254: 38.32,39.19 40.52,39.19 U5.3
  TOP w0.292: R18.2 38.32,39.19
SDA_USB_P5V_SENSE: length 17.8
  TOP w0.152: v1(43.45,29.77) 43.6,29.62 R56.2 R62.1 ; v1(42.19,41.68) U5.30
  INT_1 w0.152: v1(42.19,41.68) 42.19,35.8 42.66,35.33 42.66,34.95 43.75,33.86 43.75,32.21 43.09,31.55 43.09,30.12 v1(43.45,29.77)
  BOTTOM w0.152: v1(42.19,41.68) 43.64,41.68 TP24.1
SDA_VOUT33: length 11.1
  TOP w0.254: C6.1 33.41,43.99 34.15,43.26 v1(34.15,43.18)
  TOP w0.305: U5.5 v1(38.77,38.21)
  BOTTOM w0.254: SH16.2 36.69,40.72 34.23,43.18 v1(34.15,43.18)
  BOTTOM w0.508: v1(38.77,38.21) 37.99,38.99 SH16.2
SDA_XTAL: length 5
  TOP w0.152: U5.18 46.51,37.2 C16.1 48.03,38.02 X1.1
SI: length 2.7
  TOP w0.152: R11.2 64.27,42.85 TP9.1 65.77,42.72 U3.1
SO: length 3.5
  TOP w0.152: U3.8 73.52,42.62 TP10.1 R12.1
SW1_RST_B: length 19.1
  TOP w0.254: J5.2 19.19,48.69 19.19,45.9 18.81,45.52 13.78,45.52 12.1,47.19 C4.1 10.12,47.6 10.12,49.19 SW1.2
SWD_CLK_TGTMCU: length 37.9
  TOP w0.152: J12.4 58.28,31.65 57.8,31.17 57.8,29.16 v1(57.95,29.01) 58.31,28.65 58.31,25.53 J15.2 59.58,24.21 59.58,21.64 59,21.06 58.97,21.06 J17.2
  INT_1 w0.152: v1(66.21,35.51) 66.21,44.7 v1(66.76,45.26)
  BOTTOM w0.152: v1(57.95,29.01) 58.28,29.34 60.31,29.34 61.73,30.76 61.73,34.34 62.75,35.36 66.05,35.36 v1(66.21,35.51) ; TP22.1 67.48,45.97 v1(66.76,45.26)
SWD_CLK_TGTMCU_BUF: length 10.4
  TOP w0.152: J17.1 59.68,19.23 56.55,19.23 54.09,21.69 54.09,23.17 53.71,23.55 U14.4
SWD_DIO_TGTMCU_BUF: length 18.2
  TOP w0.152: v1(54.67,28.63) 54.46,28.84 U13.4 ; U6.2 v1(54.67,36.14) ; J16.1 57.57,22.96 56.81,23.72 56.81,26.11 v1(55.3,27.62)
  BOTTOM w0.152: v1(54.67,36.14) 54.6,36.14 53.3,34.85 53.3,29.9 54.57,28.63 v1(54.67,28.63) 54.67,28.24 v1(55.3,27.62)
TC_EXTAL_TP: length 3.4
  TOP w0.152: v1(41.69,33.73) U5.10
  BOTTOM w0.152: v1(41.69,33.73) 42.44,33.73 TP31.1
TC_XTAL_TP: length 2.3
  TOP w0.152: U5.9 41.19,35.38 40.93,35.13 v1(40.68,35.13)
  BOTTOM w0.152: TP30.1 39.83,35.13 v1(40.68,35.13)
THER_A: length 4
  TOP w0.203: R30.2 81.22,36.8 81.2,36.82 RT1.1 81.51,37.8 C15.1 R24.1
THER_B: length 3.8
  TOP w0.203: R20.1 C15.2 81.41,38.81 RT1.2 81.2,40.12 R15.1
TP_2102_A: length 3.6
  TOP w0.152: TP2.1 15.89,50.85 14.64,49.61 U1.3
TP_2102_B: length 2.1
  TOP w0.152: U1.6 12.65,51.81 TP1.1
UART0_RX_TGTMCU: length 64.5
  TOP w0.152: v2(86.65,26.52) 86.98,26.19 89.12,26.19 v2(89.37,26.44) ; U18.42 87.13,22 v2(87.06,22.07) ; J8.1 84.75,44.65 82.49,44.65 79.62,41.78 79.62,38.4 79.16,37.95 76.01,37.95 75.1,37.03 56.93,37.03 R26.2
  INT_1 w0.152: v2(89.37,26.44) 89.29,26.52 89.29,30.15 86.83,32.61 86.83,45.1 J8.1 ; v2(86.65,26.52) 86.78,26.39 86.78,24.31 87.21,23.88 87.21,22.23 v2(87.06,22.07)
UART0_TX_TGTMCU: length 61.4
  TOP w0.152: v2(86.22,26.19) 86.66,25.74 88.65,25.74 v2(88.68,25.7) ; U18.43 v2(86.63,22.4) ; R29.2 56.35,35.53 57.09,35.53 58.15,36.6 75.43,36.6 76.42,37.59 79.36,37.59 80.1,38.33 80.1,41.53 81.57,43 83.1,43 J10.1
  INT_1 w0.152: J10.1 84.54,42.32 85.43,42.32 86.4,41.35 86.4,32.54 88.79,30.15 88.79,25.83 88.68,25.73 v2(88.68,25.7) ; v2(86.22,26.19) 86.37,26.04 86.37,22.61 86.58,22.4 v2(86.63,22.4)
UART1_RX_TGTMCU_BUF: length 4
  TOP w0.152: TP15.1 53.83,38.16 U4.4 54.41,38.9 55.21,38.1 55.21,37.74 R26.1
UART1_RX_TGTMCU_R: length 10.8
  TOP w0.152: U5.25 47.47,40.86 47.97,40.36 51.04,40.36 v1(51.4,40) 51.4,39.22 51.72,38.9 U4.3
  BOTTOM w0.152: v1(51.4,40) 51.28,39.89 TP27.1
UART1_TX_TGTMCU_BUF: length 6.8
  TOP w0.152: R33.2 54.83,34.87 54.42,34.47 TP16.1 54,34.57 U6.1 54.93,35.62 55.13,35.82 55.13,36.58 55.28,36.73 56.17,36.73 R29.1
UART1_TX_TGTMCU_R: length 10.7
  TOP w0.152: U5.24 47.11,40.21 47.51,39.8 48.35,39.8 v1(49.29,38.86) 50.58,38.86 51.32,38.13 51.32,37.01 52.18,36.14 U6.6
  BOTTOM w0.152: v1(49.29,38.86) 49.44,38.71 TP26.1
V_BATT: length 38.1
  TOP w0.254: v1(40.47,16.81) R70.2
  TOP w0.508: D10.C 32.78,13.26 32.78,14.4 C56.1 33.31,14.88 34.07,14.88 35.34,16.15 39.81,16.15 v1(40.47,16.81)
  BOTTOM w0.508: v1(40.47,16.81) 43.07,16.81 47.03,20.78 48.65,20.78 52.57,16.87 59.93,16.87 61.4,15.39 J35.3
V_LDO_OUT: length 3.2
  TOP w1.016: C45.1 32.8,21.89 D8.A
V_MAIN: length 40
  TOP w0.508: J30.1 69.66,18.14 71.03,19.51 77.33,19.51 77.99,18.85 79.77,18.85 80.45,18.16 C58.1 ; J24.1 56.25,12.14 53.97,12.14 SW4.2
  TOP w1.016: J35.2 62.92,11 63.31,10.62 63.31,9.14 64.02,8.43 J27.2
  INT_1 w0.508: J24.1 58.93,13.48 J35.2
  INT_1 w1.016: J35.2 65.48,15.08 J38.3 66.62,15.74 69.02,18.14 J30.1
V_TGTMCU: length 77.5
  TOP w0.254: v1(24.65,47.52) 26.58,45.59 v1(26.58,45.09) ; U6.8 53.4,34.11 53.86,33.66 v1(53.99,33.66) 54.57,33.66 55.13,34.21 56.02,34.21 56.68,34.87 R33.1 ; 53.83,40.23 53.83,40.99 C12.1 53.91,41.15 53.51,41.55 v1(53.3,41.55) ; v1(12.43,48.26) 12.65,48.47 U1.8 12.64,49.2 C1.1 R2.1
  TOP w0.279: 53.83,40.23 U4.6
  TOP w0.305: v1(53.99,25.5) 53.61,25.12 U14.6 ; v1(53.99,30.81) 53.91,30.81 53.61,30.51 U13.6
  TOP w0.508: C26.1 v1(53.99,33.66) ; C37.1 v1(53.99,25.5) ; v1(53.99,30.81) C30.1
  INT_1 w0.254: v1(24.65,47.52) 24.4,47.78 14.19,47.78 13.73,48.23 12.46,48.23 v1(12.43,48.26)
  INT_1 w0.508: v1(53.99,25.5) 53.99,27.99 53.86,28.12 53.86,30.68 v1(53.99,30.81) v1(53.99,33.66) 53.99,41.05 53.48,41.55 v1(53.3,41.55)
  BOTTOM w0.254: v1(26.58,45.09) 44.26,45.09 47.41,41.94 53.02,41.94 53.3,41.66 v1(53.3,41.55)
  BOTTOM w0.635: SH17.1 53.25,24.77 v1(53.99,25.5)
VREFH: length 4
  TOP w0.381: J2.8 47.35,49.91 SH3.2
VREFH/VREF_OUT: length 108.9
  TOP w0.254: U18.27 91.22,16.06 v1(91.25,16.03)
  TOP w0.508: v1(92.82,12.75) C60.1 ; SH3.1 46.79,45.57 v1(46.7,45.57)
  INT_1 w0.508: v1(46.7,45.57) 46.7,44.93 49.75,41.88 49.75,40.59 51.85,38.48 51.85,31.04 50.25,29.44 50.25,26.31 53.15,23.42 55.46,23.42 56.02,22.86 56.02,21.97 54.83,20.78 50.76,20.78 47.33,17.35 47.33,9.83 48.6,8.56 54.85,8.56 58.97,4.45 86.45,4.45 88.28,6.27 90.61,6.27 93.28,8.94 93.28,12.29 v1(92.82,12.75) 92.82,14.45 v1(91.25,16.03)
VTRG_EN: length 5.2
  TOP w0.152: R53.2 R57.1 35.19,29.46 35.19,30.22 35.87,30.9 U9.3
VTRG_FAULT_B: length 16.4
  TOP w0.152: U9.4 39.42,30.9 v1(39.79,31.27) 40.14,31.62 R38.2 ; U5.32 41.19,41.71 v1(41.08,41.81)
  INT_1 w0.152: v1(39.79,31.27) 40.14,31.62 40.14,36.63 41.08,37.57 v1(41.08,41.81)
  BOTTOM w0.152: TP23.1 40.11,42.09 40.39,41.81 v1(41.08,41.81)
WP/RST: length 13.2
  TOP w0.152: R17.2 63.54,40.08 v1(64.27,40.08) 64.91,40.08 ; U3.5 v1(72.66,38.81)
  TOP w0.203: 64.91,40.08 U3.3
  BOTTOM w0.152: v1(72.66,38.81) 64.76,38.81 64.27,39.29 v1(64.27,40.08)
XTAL_32M: length 4.2
  TOP w0.152: U18.31 90.89,18.06 91.02,17.93 91.53,17.93 92.43,17.03 Y1.1
XTAL_OUT: length 12.1
  TOP w0.254: C70.2 94.07,7.87 v1(93.99,7.87) ; U18.29 91.22,17.06 v1(91.23,17.07)
  INT_1 w0.203: v1(91.23,17.07) 93.99,14.31 v1(93.99,7.87)
XTAL_OUT_CON: length 8.3
  TOP w0.254: C70.1 95.62,5.79 95.95,5.46 98.34,5.46 100.01,3.78 J33.2
N21167890: length 9.4
  TOP w0.381: J11.8 1.41,47.08
  BOTTOM w0.381: J11.8 1.41,47.06 ; J11.8 1.41,45.46 ; J11.8 2.55,46.26 ; 4.53,39.14 J11.6 3.71,39.86 ; 1.41,37.11 J11.7 ; J11.7 1.41,38.71 ; J11.7 2.55,37.91 ; 4.53,45.04 J11.9 3.71,44.31
N21328439: length 3.3
  TOP w0.152: R24.2 86.12,37.77 R25.2
  TOP w0.203: R24.2 C17.1
N21328458: length 2.9
  TOP w0.152: R20.2 86.14,38.81 R19.2
  TOP w0.203: C14.1 R20.2
N21328514: length 3.4
  TOP w0.508: Q4.3 34.56,10.17 34.56,11.13 34.99,11.56 R88.1
N21337706: length 4.1
  TOP w0.508: D2.C R27.2 R34.2
N21361580: length 4.1
  TOP w0.508: C63.2 5.65,13.69 R77.1 R73.2
N21445715: length 2.3
  TOP w0.152: TP13.1 5.91,41.2 5.67,41.44 J11.4
N21455862: length 3.2
  TOP w0.254: Q1.1 48.93,15.01 R80.2 R76.2
N21456098: length 1.6
  TOP w0.254: R87.1 45.82,15.93 Q1.3
N21456788: length 3.3
  TOP w0.254: R82.1 R85.1 48.81,11.07 Q2.1
N21456802: length 3.3
  TOP w0.254: R90.1 44.31,11.63 44.69,12.01 Q2.3
N21456812: length 3
  TOP w0.254: R89.1 R94.2 48.96,7.14 Q3.1
N21456830: length 4.8
  TOP w0.254: R93.1 45.35,6.93 45.83,7.42 45.83,8.06 Q3.3
N21501528: length 3.2
  TOP w0.254: Q4.1 R98.2 R92.2
N21519740: length 29.5
  TOP w0.508: SH12.2 43.14,19.41 v1(44.26,19.41)
  BOTTOM w0.508: v1(44.26,19.41) 40.75,19.41 39.28,17.93 39.28,15.32 43.66,10.94 J24.2
N21560793: length 2.2
  TOP w0.152: U7.1 19.71,34.58 R35.1
N21560827: length 3.5
  TOP w0.152: J39.1 18.43,37.39 R50.2
N21560833: length 2.4
  TOP w0.152: R58.1 20.33,28.37 19.44,29.27 U12.4
N21560903: length 2
  TOP w0.152: R28.1 19.81,35.23 19.68,35.1 U7.2
N21561545: length 2.3
  TOP w0.152: U17.5 20.21,18.47 R71.2
N21561559: length 2.4
  TOP w0.152: R74.1 20.08,17.32 19.44,17.97 U17.4
N21611491: length 2.1
  TOP w0.152: U20.4 19.56,15.04 R81.1
N21837447: length 2.1
  TOP w0.203: R72.1 105.42,19.08 C52.1 C55.2
N21928909: length 11.8
  TOP w0.254: U12.5 19.62,29.77 20.03,29.36 21.68,29.36 v1(22.59,30.28)
  INT_1 w0.254: v1(22.59,30.28) 22.59,35.08 23.71,36.2 J39.2
N21929178: length 2.6
  TOP w0.152: J39.3 28.18,37.39 R101.1
N213293921: length 1.5
  TOP w0.508: LED3.C R88.2
N215011841: length 1.9
  TOP w0.254: LED2.C 37.06,17.46 R75.1

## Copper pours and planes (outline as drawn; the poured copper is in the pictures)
GND on TOP: 46.65,37.52 46.65,36.12 47.46,35.31 50.79,35.31 50.79,38.15 47.28,38.15
GND on TOP: 6.35,0.3 2.08,2.08 0.3,6.35 0.3,46.99 2.08,51.26 6.35,53.04 85.57,53.06 88.11,53.06 90.65,53.06 93.18,53.06 95.72,53.06 98.26,53.06 100.8,53.06 102.97,53.06 105.51,53.06 108.27,53.06 108.27,0.3 ; 24 cut-outs
GND on BOTTOM: 6.35,0.3 2.08,2.08 0.3,6.35 0.3,46.99 2.08,51.26 6.35,53.04 85.57,53.06 88.11,53.06 90.65,53.06 93.18,53.06 95.72,53.06 98.26,53.06 100.8,53.06 102.97,53.06 105.51,53.06 108.27,53.06 108.27,0.3 ; 3 cut-outs
GND on GND: 6.35,0.3 2.08,2.08 0.3,6.35 0.3,46.99 2.08,51.26 6.35,53.04 85.57,53.06 88.11,53.06 90.65,53.06 93.18,53.06 95.72,53.06 98.26,53.06 100.8,53.06 102.97,53.06 105.51,53.06 108.27,53.06 108.27,0.3 ; 1 cut-out
GND on INT_1: 6.35,0.3 2.08,2.08 0.3,6.35 0.3,46.99 2.08,51.26 6.35,53.04 85.57,53.06 88.11,53.06 90.65,53.06 93.18,53.06 95.72,53.06 98.26,53.06 100.8,53.06 102.97,53.06 105.51,53.06 108.27,53.06 108.27,0.3 ; 9 cut-outs
P3V3_SDA on TOP: 40.88,40.15 37.07,40.16 36.28,40.94 36.28,42.02 40.88,42.01
P5V on TOP: 8.52,22.66 7.89,23.29 7.89,27.1 9.28,27.1 9.28,25.07 10.81,25.07 11.06,24.82 11.06,22.78 10.93,22.66
P5V on INT_1: 13.22,15.67 10.05,18.85 7.76,18.85 7.12,19.48 7.12,26.85 7.63,27.36 10.17,27.36 14.24,31.42 14.24,32.92 16.55,35.23 16.55,36.96 17.23,37.64 18.22,37.64 18.94,36.93 18.94,33.96 22.11,30.78 22.11,16.69 21.09,15.67
P5V_LDO_OUT on TOP: 28.87,6.81 28.87,5.38 27.6,4.11 27.6,2.26 25.36,2.26 25.29,2.34 25.29,4.83 24.15,4.83 23.7,5.28 23.7,6.64 23.86,6.81
P5V_SDA on TOP: 32.5,30.23 32.5,35.26 32.52,35.28 34.02,35.28 34.02,38.23 33.67,38.58 33.67,39.78 33.69,39.8 33.97,39.8 35.42,38.35 35.42,34.92 36.16,34.92 36.16,34.11 35.42,34.11 35.42,32.49 35.29,32.36 33.29,32.36 33.29,31.5 33.39,31.39 34.51,31.39 34.51,30.3 34.43,30.23
P5V_USB on TOP: 26.76,32.89 30.39,32.89 30.39,29.92 27.01,29.92 26.73,30.2 26.73,32.87
P12V_VBAT on TOP: 8.6,11.07 8.24,11.43 8.24,13.13 8.6,13.49 10.2,13.49 11.6,14.88 11.6,20.04 10.27,21.36 7.58,21.36 5.68,23.27 5.68,26.82 7.2,28.35 9,28.35 9.49,28.83 9.49,29.49 9.41,29.57 9.41,30.66 9.54,30.78 9.69,30.78 10.22,31.32 10.22,33.71 12.05,35.53 12.05,37.95 12.46,38.35 14.19,38.35 14.9,37.64 14.9,35.36 14.06,34.52 13.53,34.52 11.47,32.46 11.47,29.13 9.59,27.25 7.84,27.25 7.18,26.59 7.18,23.72 8.45,22.45 15.2,22.45 15.48,22.17 15.48,20.29 14.74,19.56 14.47,19.56 13.22,18.31 13.22,13.72 10.58,11.07
P5-9V_VIN on TOP: 29.43,6.5 34.99,6.5 34.99,5.51 33.46,3.99 33.46,2.31 33.44,2.29 30.7,2.29 30.7,4.29 29.43,5.56
P5-9V_VIN_VR on TOP: 23.1,24.84 23.1,35.31 25.95,35.31 25.95,25.93 25.29,25.27 25.29,24.84
RF_ANT on TOP (solid shape): 109.37,18.66 108.51,18.66 107.06,18.97 107.06,19.17 108.51,19.51 109.37,19.51
V_LDO_OUT on TOP: 24.27,14.53 24.09,14.71 24.09,19.56 25.79,21.26 25.79,23.93 25.92,24.05 27.19,24.05 27.7,23.55 27.7,21.13 27.83,21.01 30.11,21.01 30.37,21.26 30.37,22.15 30.75,22.53 32.78,22.53 33.03,22.28 33.03,19.99 32.65,19.61 29.98,19.61 28.84,18.47 28.84,14.78 28.59,14.53
V_MAIN on TOP: 83.63,16.71 82.13,16.71 81.01,17.83 81.01,18.11 80.81,18.31 80.33,18.31 80,17.98 80,17.3 80.38,16.92 80.99,16.92 81.5,16.41 83.6,16.41 83.68,16.48 83.68,16.66
N21167890 on TOP: 0.42,45.95 0.39,45.97 0.39,48.02 0.52,48.6 0.71,49.16 1.08,49.53 2.07,49.53 2.22,49.38 2.22,47.8 2.17,47.75 2.17,47.32 2.58,46.91 2.58,46.18 2.35,45.95
N21167890 on BOTTOM: 5.4,44.04 5.4,46.3 4.28,47.42 0.67,47.42 0.34,47.09 0.34,37.13 0.52,36.96 3.82,36.96 5.37,38.51 5.37,40.11 4.99,40.49 3.47,40.49 3.24,40.72 3.24,43.51 3.44,43.71 5.07,43.71

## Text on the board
BOTTOM: 170-43110 REV B | 7 OF 10 | SECONDARY SIDE
Ref Des/Assembly Bottom: 2 OF 2 | SECONDARY ASSEMBLY
Ref Des/Silkscreen Bottom: SCH-43110 | 700-43110 | 5V EXT GEN | J2 | J3 | J1 | J4 | PTB0 | PTB1 | VREFH | GND | PTC16 | PTC18 | PTC17 | PTA19 | PTC1 | PTA16 | PTC5 | PTA18 | PTC4 | PTA17 | PTC3 | PTC19 | PTC7 | PTC6 | OpenSDA | NC | P1V8_3V3_BRD | RESET/PTA2 | P5V_USB | P5-9V_VIN | ADC0_DM0 | PTB18 | PTB2 | PTB3 | ADC0_DP0/PTB0 | 10 OF 10 | SECONDARY SILKSCREEN
User.Comments: 8 OF 10 | SECONDARY SOLDERMASK | 1 OF 1 | TEST PROBE | 1/1 | 1
TOP: 4 OF 10 | PRIMARY SIDE
Ref Des/Assembly Top: 1 OF 2 | PRIMARY ASSEMBLY
Board Geometry/Soldermask Top: 3 OF 10 | PRIMARY SOLDERMASK
Ref Des/Silkscreen Top: SMA | RST | SDA | PSWITCH | KW37 | SWD | MKW38 | LLWU | NMI | GND | NC | CAN_H | CAN_L | P12V | LIN | SDA_JTAG | F-ANTENNA | 1 OF 10 | PRIMARY SILKSCREEN | FRDM- | KW38
GND: 5 OF 10 | L2_GND
INT_1: 6 OF 10 | L3_INT_1
DIMENSION: A - TARGET : 4.685 MILS 2116(57%)*1 | B - TARGET : 46.85 MILS | C - TARGET : 4.685MILS 2116(57%)*1 | 50 OHMS SINGLE ENDED | J24 PIN1 & PIN2 | J29, J31 J16, J17, J8, J10, J9, J7 ARE SHORT INTERNALLY | RF_ANT  & GDN | J15 SWD_CLK_TGTMCU_BUF & SWD_CLK_TGTMCU | J6 SDA_RST_TGTMCU_J_B & SDA_RST_TGTMCU_B | J38 PIN2 & PIN3 | SH1~SH17 ARE SHORT INTERNALLY | 23. INTENTIONAL SHORT ON TOP LAYER BETWEEN RF_ANT AND GND | 24. OVERALL PCB DIELECTRIC THICKNESS ARE TARGETED (A & C) 10 MILS+/-10% AND (B) 38 MILS +/-10% | 22. INTENTIONAL SHORTS AT: | AS SHOWN IN DETAIL 'A'. ADJUSTEMENT IN SUBSTRATE B IS ALLOWED TO MEET OVERALL HEIGHT REQUIREMENT. | Er - MUST BE FROM 4.2 TO 4.4 | 24 | 16 | 23 | 17 | 8 | DETAIL B | GRID ORIGIN | PRIMARY DATUM
DISPLAY_TOP: 2 OF 10 | PASTEMASK TOP
COMPVAL_TYPE_TOP: 9 OF 10 | SECONDARY PASTEMASK
User.16: 01-17-19 | 01-24-19 | 07-08-19 | A | B | PROTOTYPE RELEASE | PWR LINE & DCDC LAYOUT UPDATED
User.22: FIGURE | FINISHED_SIZE | 8.0 | 10.0 | 12.0 | 26.0 | 40.0 | 41.0 | 63.0 | 100.0 | 125.0 | 34.0x26.0 | 59.0x33.0 | 111.0x32.0 | 122.0x32.0 | DRILL CHART: TOP to BOTTOM | ALL UNITS ARE IN MILS | TOLERANCE_DRILL | +0.0/-8.0 | +3.0/-3.0 | +0.0/-10.0 | +2.0/-2.0 | PLATED | NON-PLATED | QTY | 696 | 26 | 758 | 2 | 20 | 8 | 56 | 16 | 6 | 1 | 4 | 3
